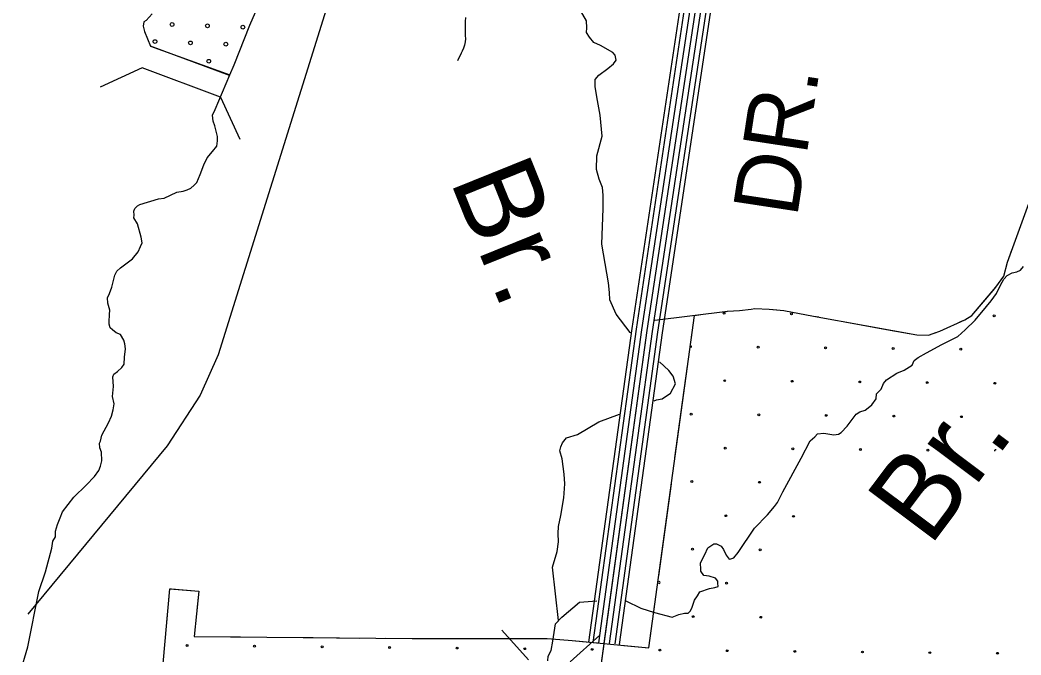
# Model space of a CAD drawing. Extents: x 1577619 to 1828281, y 483481 to 598136.
# Drawn here: x 1675674 to 1681374, y 518314 to 521931 of the extents above; entities that cross this region are included whole.
import ezdxf

# ---------------------------------------------------------------- set-up
doc = ezdxf.new("R2010")
doc.units = 0
for name, color, linetype in [('DESIGN - DRAINAGE - Bridges and Cross Drains Size Text', 7, 'Continuous'), ('DESIGN - EROSION CONTROL - Devices', 7, 'Continuous'), ('DESIGN - ROW - Right-of-Way and Easement Labels', 7, 'Continuous'), ('DESIGN - TRAFFIC CONTROL PERMANENT - Pavement Marking Text', 7, 'Continuous'), ('DESIGN - TRANSPORTATION - Edge of Traveled Way', 7, 'Continuous'), ('DESIGN - TRANSPORTATION - Text', 7, 'Continuous'), ('SURVEY - CENTERLINE - Preliminary Text', 7, 'Continuous'), ('SURVEY - DRAINAGE - Area Shapes', 7, 'Continuous'), ('SURVEY - DRAINAGE - Storm Sewer', 7, 'Continuous'), ('SURVEY - PROPERTY - Owners', 7, 'Continuous'), ('SURVEY - TRANSPORTATION - Roads', 7, 'Continuous'), ('SURVEY - VEGETATION - Features with Text', 7, 'Continuous')]:
    doc.layers.add(name, color=color, linetype=linetype)

msp = doc.modelspace()

# ---------------------------------------------------------------- linework, layer by layer
at = {"layer": 'DESIGN - EROSION CONTROL - Devices'}
for centre in [(1679682.6, 520261.1), (1680067.1, 520257.4), (1681220.8, 520246.2), (1679876.7, 520066.9), (1680261.3, 520063.2), (1680645.8, 520059.5), (1681030.4, 520055.7), (1679686.3, 519876.5), (1680070.8, 519872.8), (1680455.4, 519869.1), (1680840, 519865.3), (1681224.5, 519861.6), (1679495.9, 519686.1), (1679880.4, 519682.4), (1680265, 519678.7), (1680649.5, 519674.9), (1681034.1, 519671.2), (1679690, 519492), (1680074.6, 519488.2), (1680459.1, 519484.5), (1680843.7, 519480.8), (1679499.6, 519301.6), (1679884.2, 519297.8), (1679693.8, 519107.4), (1680078.3, 519103.7), (1679503.4, 518917), (1679887.9, 518913.3), (1679697.5, 518722.9), (1679507.1, 518532.5), (1679891.6, 518528.7), (1676624.8, 518368.2), (1677009.4, 518364.5), (1677393.9, 518360.7), (1677778.5, 518357), (1678163, 518353.3), (1678547.6, 518349.5), (1678932.1, 518345.8), (1679316.7, 518342.1), (1679701.2, 518338.3), (1680085.8, 518334.6), (1680470.3, 518330.9), (1680854.9, 518327.1), (1681239.4, 518323.4)]:
    msp.add_circle(centre, 5.28, dxfattribs=at)
for centre, start, end in [((1679492.1, 520070.7), 282.9863, 61.3706), ((1681228.2, 519477), 36.5337, 193.1012), ((1679312.9, 518726.6), 220.742, 123.6149)]:
    msp.add_arc(centre, 5.28, start, end, dxfattribs=at)
at = {"layer": 'DESIGN - TRAFFIC CONTROL PERMANENT - Pavement Marking Text'}
for centre in [(1676539.6, 521905.2), (1676741.2, 521897.7), (1676942.8, 521890.2), (1676442.5, 521808.1), (1676644.1, 521800.6), (1676845.7, 521793.2), (1676748.6, 521696.1)]:
    msp.add_circle(centre, 10.6, dxfattribs=at)
at = {"layer": 'DESIGN - TRANSPORTATION - Edge of Traveled Way'}
for p, q in [((1676867.1, 521614.2), (1676416.1, 521781.6)), ((1676370.2, 521657.9), (1676130.2, 521547.9)), ((1676816.2, 521492.3), (1676370.2, 521657.9)), ((1676816.2, 521492.3), (1676926.2, 521252.3))]:
    msp.add_line(p, q, dxfattribs=at)
at = {"layer": 'DESIGN - TRANSPORTATION - Text'}
for points in [[(1676868.6, 521618.4), (1676893.3, 521676.4), (1676981.7, 521902.1), (1677047.3, 522051.8)], [(1679031.9, 520336.8), (1679030.8, 520378.5), (1679025.4, 520434.7), (1678987.7, 520653.7), (1678993.9, 520858.1), (1678994.7, 520932.3), (1678991.1, 520976.5), (1678971.6, 521024.8), (1678956.2, 521079.1), (1678959, 521157.3), (1678988.2, 521269.3), (1678977.5, 521389.8), (1678958.6, 521494.2), (1678949.2, 521552.5), (1678949.6, 521592.6), (1678969.9, 521616.5), (1679020.3, 521654), (1679052.6, 521681.8), (1679068.8, 521701.6), (1679063.1, 521729.8), (1679049.3, 521746), (1678979.7, 521784.8), (1678941.8, 521803.3), (1678916.1, 521833.6), (1678900.4, 521859.8), (1678900.7, 521885.9), (1678899.1, 521926), (1678865.7, 521984.5)], [(1676426.1, 521966), (1676391.7, 521928.3), (1676379.6, 521920.4), (1676375.3, 521896.4), (1676383, 521866.2), (1676416.1, 521781.6), (1676868.6, 521618.4)], [(1676770.2, 521388.9), (1676784.5, 521420.8), (1676868.6, 521618.4)], [(1675673.9, 518211.7), (1675717.5, 518359.7), (1675780.9, 518675.9), (1675818.1, 518787.8), (1675855.5, 518921.7), (1675859.9, 518961.8), (1675876.2, 518987.7), (1675876.6, 519019.8), (1675887, 519057.8), (1675903.4, 519095.7), (1675915.7, 519129.7), (1675980.7, 519213.2), (1676051.4, 519280.7), (1676098, 519330.3), (1676122.4, 519364.2), (1676132.6, 519390.1), (1676139, 519420.1), (1676137.5, 519468.3), (1676127.7, 519494.5), (1676126, 519520.5), (1676132.1, 519532.5), (1676140.5, 519566.5), (1676177.3, 519636.3), (1676195.7, 519674.2), (1676204.1, 519710.2), (1676210.4, 519744.3), (1676200.9, 519786.5), (1676205.5, 519842.6), (1676202.1, 519898.8), (1676208.2, 519912.8), (1676228.4, 519928.6), (1676252.7, 519952.4), (1676266.8, 519970.3), (1676269.3, 520010.4), (1676273.8, 520058.5), (1676270.1, 520086.6), (1676264.3, 520106.7), (1676246.6, 520139), (1676220.7, 520149.3), (1676200.9, 520165.5), (1676187, 520177.7), (1676181.2, 520197.8), (1676181.4, 520211.8), (1676183.8, 520253.9), (1676186.1, 520278), (1676174.5, 520318.2), (1676172.8, 520348.3), (1676183.1, 520372.3), (1676197.5, 520408.2), (1676205.9, 520446.2), (1676214.2, 520478.2), (1676224.4, 520500.2), (1676246.7, 520520), (1676315.2, 520571.4), (1676345.7, 520611.2), (1676360, 520641.1), (1676370.2, 520661.1), (1676364.6, 520693.2), (1676343.4, 520769.7), (1676321.7, 520804), (1676323.9, 520820), (1676322.1, 520842.1), (1676328.3, 520858.1), (1676342.4, 520872), (1676356.5, 520879.8), (1676462.9, 520912.8), (1676495, 520916.5), (1676567.4, 520949.8), (1676603.5, 520955.4), (1676625.6, 520963.2), (1676645.7, 520973), (1676665.9, 520990.9), (1676680, 521004.8), (1676700.5, 521050.7), (1676721.1, 521106.6), (1676739.6, 521146.5), (1676770, 521182.3), (1676794.3, 521212.1), (1676798.6, 521242.2), (1676798.9, 521268.2), (1676783.5, 521328.6), (1676773.8, 521354.7), (1676770.2, 521388.9)], [(1681275, 520455.2), (1681295.2, 520475), (1681323.4, 520490.8), (1681349.4, 520496.5), (1681371.6, 520506.3), (1681387.8, 520526.2)], [(1679123.7, 518622.8), (1679208.7, 518581.5), (1679286.7, 518556.7), (1679387.5, 518529.7), (1679425.6, 518545.4), (1679457.7, 518553), (1679477.8, 518552.8), (1679491.9, 518564.7), (1679502.1, 518586.7), (1679514.6, 518626.6), (1679530.8, 518650.5), (1679545.1, 518674.5), (1679599.3, 518691.9), (1679629.4, 518697.6), (1679649.5, 518703.4), (1679647.7, 518723.5), (1679647.8, 518733.5), (1679634, 518751.7), (1679598, 518762.1), (1679568.1, 518766.5), (1679550.3, 518790.7), (1679550.4, 518800.7), (1679548.8, 518838.9), (1679573.3, 518886.7), (1679589.8, 518924.7), (1679624, 518946.4), (1679640, 518946.2), (1679665.9, 518933.9), (1679679.7, 518915.7), (1679695.4, 518883.4), (1679711.1, 518859.2), (1679721.2, 518861.1), (1679739.2, 518866.9), (1679763.6, 518896.8), (1679857.1, 519036.2), (1679929.9, 519111.6), (1679970.5, 519159.3), (1679986.7, 519183.2), (1680017.4, 519243), (1680121.5, 519434.5), (1680172.6, 519534.2), (1680198.8, 519556), (1680215, 519573.9), (1680251.1, 519577.5), (1680307, 519568.9), (1680335.1, 519572.6), (1680349.2, 519580.5), (1680383.6, 519618.2), (1680434.3, 519685.9), (1680456.5, 519699.7), (1680486.6, 519709.4), (1680512.8, 519729.2), (1680524.9, 519739.1), (1680549.3, 519772.9), (1680551.6, 519801), (1680577.9, 519828.8), (1680590.3, 519860.7), (1680608.5, 519880.6), (1680666.9, 519920.1), (1680709.1, 519935.7), (1680753.5, 519965.3), (1680765.7, 519991.2), (1680787.9, 520009.1), (1680836.2, 520034.6), (1680922.8, 520081.8), (1681013.3, 520129), (1681055.8, 520166.7), (1681112.4, 520220.2), (1681177.2, 520299.8), (1681203.6, 520331.6), (1681234.1, 520373.4), (1681252.5, 520413.3), (1681266.8, 520437.2), (1681275, 520455.2)], [(1679150.7, 520148.6), (1679147.8, 520151.4), (1679068.7, 520255.2), (1679031.9, 520336.8)], [(1679330.6, 519773.3), (1679377.5, 519805.4), (1679405.9, 519858.8), (1679393.7, 519903), (1679369.1, 519934.9), (1679315.5, 519984.1)], [(1679284.8, 519761.9), (1679298.5, 519767.2), (1679330.6, 519773.3)], [(1678740.5, 518510), (1678705.4, 518813.4), (1678732.3, 518903.3), (1678740.9, 518959.4), (1678737.4, 519005.5), (1678739.8, 519045.6), (1678752.5, 519107.7), (1678769.6, 519209.8), (1678776.4, 519287.9), (1678773, 519344.1), (1678761.9, 519430.4), (1678748.4, 519476.7), (1678752.6, 519498.7), (1678762.9, 519522.7), (1678785.2, 519550.5), (1678847.4, 519569.9), (1678849, 519569.9), (1678969.9, 519641.1), (1679087.1, 519686.1)], [(1678678.7, 518281.2), (1678680.8, 518307.8), (1678699.1, 518339.7), (1678708, 518392.5), (1678722.2, 518491.7), (1678760, 518529.5), (1678859.2, 518614.5), (1678958.4, 518622.8)]]:
    msp.add_lwpolyline(points, dxfattribs=at)
at = {"layer": 'SURVEY - CENTERLINE - Preliminary Text'}
for points in [[(1681695, 533313.3), (1681214.7, 531661.5), (1681112.7, 531483.8), (1680721.5, 531075.8), (1680358.7, 530689.6), (1680210.6, 530522.4), (1680066.1, 530306.8), (1679906.2, 529952.9), (1676801.4, 520023.1), (1676698.9, 519793.1), (1676511.6, 519505.7), (1675717.5, 518546.5)], [(1681695, 533313.3), (1681214.7, 531661.5), (1681112.7, 531483.8), (1680721.5, 531075.8), (1680358.7, 530689.6), (1680210.6, 530522.4), (1680066.1, 530306.8), (1679906.2, 529952.9), (1676801.4, 520023.1), (1676698.9, 519793.1), (1676511.6, 519505.7), (1675717.5, 518546.5)], [(1678829.9, 526510.7), (1676801.4, 520023.1), (1676698.9, 519793.1), (1676511.6, 519505.7), (1675717.5, 518546.5)], [(1678829.9, 526510.7), (1676801.4, 520023.1), (1676698.9, 519793.1), (1676511.6, 519505.7), (1675717.5, 518546.5)]]:
    msp.add_lwpolyline(points, dxfattribs=at)
at = {"layer": 'SURVEY - DRAINAGE - Area Shapes'}
msp.add_lwpolyline([(1678966.7, 518137.3), (1678967.1, 518141.1), (1678999.9, 518379.9)], dxfattribs=at)
at = {"layer": 'SURVEY - DRAINAGE - Storm Sewer'}
for p, q in [((1678568.7, 518287), (1678416.8, 518455.7)), ((1678806, 518274.5), (1678974.8, 518426.5))]:
    msp.add_line(p, q, dxfattribs=at)
at = {"layer": 'SURVEY - PROPERTY - Owners'}
msp.add_lwpolyline([(1678966.7, 518137.3), (1678967.1, 518141.1), (1679244.6, 520161.6), (1679530.9, 522061.8), (1679782.5, 523707.6), (1679840.5, 524082), (1679862.5, 524268.3), (1679877.5, 524360.4), (1679886.2, 524432.5), (1679884.8, 524488.7), (1679875.8, 524548), (1679866, 524603.2), (1679837.1, 524707.8), (1679808.9, 524865)], dxfattribs=at)
at = {"layer": 'SURVEY - TRANSPORTATION - Roads'}
for points in [[(1678913.3, 518386.8), (1679158.8, 520174), (1679445.2, 522074.8), (1679696.8, 523720.8), (1679754.6, 524093.8), (1679776.6, 524280.4), (1679791.6, 524372.6), (1679799.4, 524436.7), (1679798.3, 524481.1), (1679790.3, 524533.9), (1679781.4, 524584), (1679752.5, 524688.5), (1679723.5, 524849.6)], [(1678938.1, 518385.7), (1679183.3, 520170.5), (1679469.6, 522071.1), (1679721.2, 523717), (1679779.1, 524090.4), (1679801.1, 524276.9), (1679816.1, 524369.1), (1679824.1, 524435.5), (1679822.9, 524483.2), (1679814.7, 524537.9), (1679805.5, 524589.4), (1679776.6, 524694), (1679747.8, 524854)], [(1678966.7, 518137.3), (1678967.1, 518141.1), (1679244.6, 520161.6), (1679530.9, 522061.8), (1679782.5, 523707.6), (1679840.5, 524082), (1679862.5, 524268.3), (1679877.5, 524360.4), (1679886.2, 524432.5), (1679884.8, 524488.7), (1679875.8, 524548), (1679866, 524603.2), (1679837.1, 524707.8), (1679808.9, 524865)], [(1678969.1, 518383.4), (1679214, 520166), (1679500.3, 522066.4), (1679751.9, 523712.3), (1679809.8, 524086.2), (1679831.8, 524272.6), (1679846.8, 524364.8), (1679855.2, 524434), (1679853.9, 524486), (1679845.3, 524543), (1679835.8, 524596.3), (1679806.9, 524700.9), (1679778.4, 524859.5)], [(1679000, 518380.8), (1679244.6, 520161.6), (1679530.9, 522061.8), (1679782.5, 523707.6), (1679840.5, 524082), (1679862.5, 524268.3), (1679877.5, 524360.4), (1679886.2, 524432.5), (1679884.8, 524488.7), (1679875.8, 524548), (1679866, 524603.2), (1679837.1, 524707.8), (1679808.9, 524865)], [(1679031.1, 518379.3), (1679275.3, 520157.2), (1679561.6, 522057.1), (1679813.1, 523702.9), (1679871.2, 524077.8), (1679893.2, 524264), (1679908.2, 524356), (1679917.3, 524431), (1679915.8, 524491.4), (1679906.4, 524553), (1679896.3, 524610), (1679867.4, 524714.6), (1679839.4, 524870.5)], [(1679062.1, 518376.9), (1679306, 520152.8), (1679592.2, 522052.5), (1679843.8, 523698.2), (1679901.9, 524073.6), (1679923.9, 524259.7), (1679938.9, 524351.7), (1679948.3, 524429.5), (1679946.7, 524494.1), (1679937, 524558.1), (1679926.6, 524616.9), (1679897.6, 524721.5), (1679869.9, 524875.9)], [(1679087.5, 518373.1), (1679331.5, 520149.1), (1679617.7, 522048.6), (1679869.2, 523694.3), (1679927.4, 524070.2), (1679949.4, 524256.1), (1679964.3, 524348.1), (1679974.1, 524428.3), (1679972.4, 524496.4), (1679962.4, 524562.3), (1679951.7, 524622.6), (1679922.7, 524727.2), (1679895.2, 524880.5)], [(1678210.2, 521944.3), (1678209.4, 521922.5), (1678209.2, 521899.2), (1678208.7, 521877), (1678208.8, 521859.9), (1678209.2, 521843.5), (1678209.6, 521823.5), (1678208.8, 521805.7), (1678205.7, 521788.2), (1678199.6, 521770.8), (1678191.7, 521753), (1678186.3, 521742.5), (1678164.2, 521697.6)]]:
    msp.add_lwpolyline(points, dxfattribs=at)
at = {"layer": 'SURVEY - VEGETATION - Features with Text'}
for points in [[(1679288.1, 520220.6), (1679702.3, 520271.6), (1679770.6, 520276.8), (1679836.6, 520284.6), (1679858.9, 520288), (1679940, 520284.3), (1680023.5, 520275.3), (1680192.8, 520244.6), (1680779.7, 520137.8), (1680846.5, 520136.2), (1680912.4, 520158.5), (1681053.9, 520223.9), (1681093.6, 520248), (1681231, 520409.5), (1681276.3, 520472.4), (1681296.9, 520550.7), (1681555.5, 521261.6)], [(1681214.5, 520390.1), (1681231, 520409.5), (1681276.3, 520472.4), (1681296.9, 520550.7), (1681324.3, 520626)], [(1681025.8, 520210.9), (1681053.9, 520223.9), (1681093.6, 520248), (1681214.5, 520390.1)], [(1679699, 520271.2), (1679702.3, 520271.6), (1679770.6, 520276.8), (1679836.6, 520284.6), (1679858.9, 520288), (1679940, 520284.3), (1679961.8, 520281.9)], [(1679961.8, 520281.9), (1680023.5, 520275.3), (1680192.8, 520244.6), (1680222.2, 520239.3)], [(1679254.5, 518355.1), (1679514.6, 520248.5)], [(1679495.4, 520108.6), (1679514.6, 520248.5)], [(1679514.6, 520248.5), (1679550.1, 520252.8)], [(1680369.8, 520212.4), (1680629.5, 520165.1)], [(1680629.5, 520165.1), (1680779.7, 520137.8), (1680846.5, 520136.2), (1680888.6, 520150.5)], [(1679439.1, 519698.4), (1679475, 519960)], [(1679403.1, 519436.9), (1679439.1, 519698.5)], [(1679346.8, 519026.7), (1679382.7, 519288.3)], [(1679310.9, 518765.2), (1679346.8, 519026.8)], [(1676406.6, 517349.5), (1676527.4, 518691.2), (1676691.2, 518676.8), (1676665.7, 518419.2)], [(1676504.5, 518437.1), (1676527.4, 518691.2), (1676536.2, 518690.4)], [(1676536.2, 518690.4), (1676691.2, 518676.8), (1676680.5, 518568.9)], [(1679254.5, 518355.1), (1679290.4, 518616.6)], [(1676665.8, 518419.6), (1676665.7, 518419.2)], [(1676665.7, 518419.2), (1677906.9, 518407.6), (1678676.5, 518408.4), (1678817.9, 518396.4), (1679254.5, 518355.1)], [(1676665.7, 518419.2), (1676929.7, 518416.7)], [(1677079.7, 518415.3), (1677343.7, 518412.9)], [(1677343.7, 518412.9), (1677607.7, 518410.4)], [(1677757.7, 518409), (1677906.9, 518407.6), (1678021.6, 518407.7)], [(1678021.6, 518407.7), (1678285.6, 518408)], [(1678435.6, 518408.2), (1678676.5, 518408.4), (1678699.5, 518406.5)], [(1678699.5, 518406.5), (1678817.9, 518396.4), (1678962.4, 518382.7)], [(1679111.8, 518368.6), (1679254.5, 518355.1)]]:
    msp.add_lwpolyline(points, dxfattribs=at)

# ---------------------------------------------------------------- texts
at = {"layer": 'DESIGN - DRAINAGE - Bridges and Cross Drains Size Text'}
for height, rotation, p in [(475.01, 291.9705, (1678120, 521018.8)), (475, 53.1247, (1680853.6, 518924.9))]:
    msp.add_text('Br.', height=height, rotation=rotation, dxfattribs=at).set_placement(p)
at = {"layer": 'DESIGN - ROW - Right-of-Way and Easement Labels'}
msp.add_text('DR.', height=370.01, rotation=81.3096, dxfattribs=at).set_placement((1680097.8, 520800.3))

doc.saveas('drawing.dxf')
